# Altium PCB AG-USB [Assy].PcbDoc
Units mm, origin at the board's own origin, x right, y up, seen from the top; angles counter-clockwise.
Board outline 22 x 85.18 mm, 2 copper layers (Top Layer, Bottom Layer), stack 1.571 mm thick; 0 components, 8 nets, 0 pads, 0 vias.
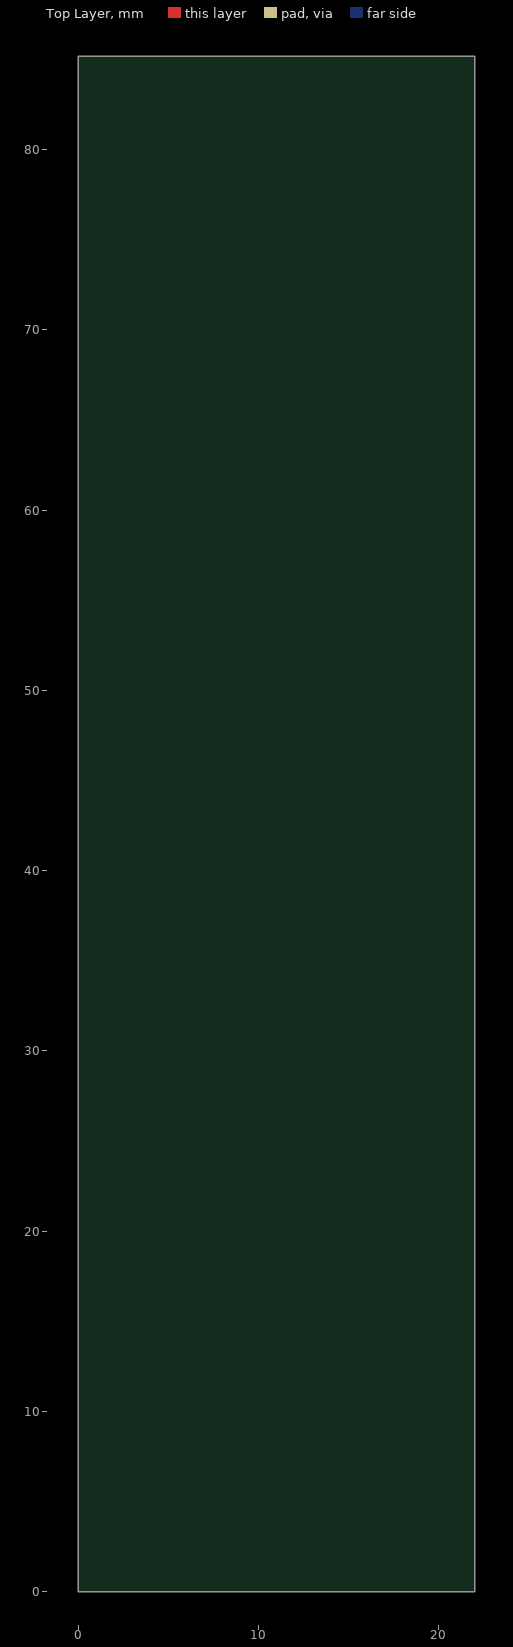
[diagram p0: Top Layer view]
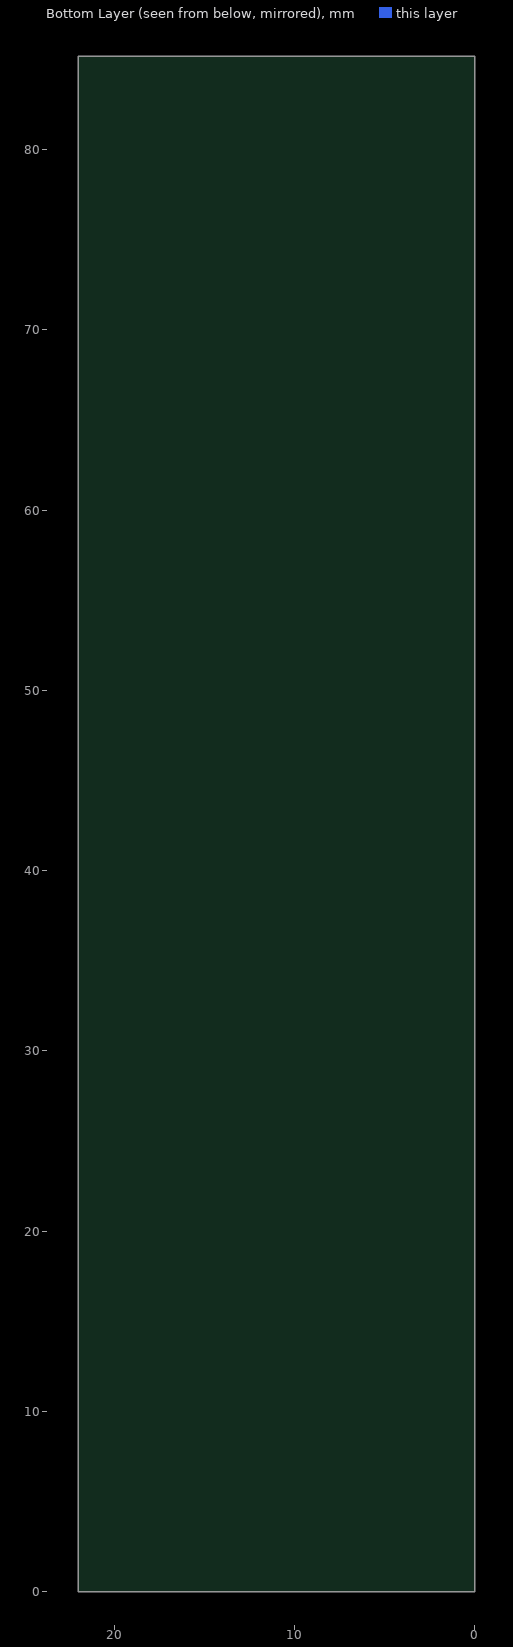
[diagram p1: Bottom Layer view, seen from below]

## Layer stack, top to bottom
Top Layer: signal copper 0.0356
Dielectric: prepreg 1.5, FR-4, Dk 4.2
Bottom Layer: signal copper 0.0356

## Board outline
0,0 0,85.18 22,85.18 22,0

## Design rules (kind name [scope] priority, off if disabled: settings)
Clearance [All] p1: gap=0.17
FabricationTestPointUsage TestPointUsage [All] p1: valid=0 allowmultiple=FALSE
FabricationTestpoint Testpoint [All] p1: side=3 testpointundercomponent=TRUE minsize=1.016 maxsize=2.54 preferedsize=1.524 minholesize=0 maxholesize=1.016 preferedholesize=0.813 testpointgrid=0.025 allowsidetop=TRUE allowsidebottom=TRUE usegrid=TRUE gridtolerance=0
HoleSize [All] p1: absolutevalues=TRUE maxlimit=5 minlimit=0.25 maxpercent=80.000 minpercent=20.000
PlaneClearance [All] p1: clearance=0.5
PolygonConnect PolygonConnectVia [All vs isvia] p1: connectstyle=Direct reliefconductorwidth=0.25 reliefentries=4 polygonreliefangle="90 Angle" airgapwidth=0.254
PolygonConnect [All] p2: connectstyle=Relief reliefconductorwidth=0.4 reliefentries=4 polygonreliefangle="90 Angle" airgapwidth=0.254
RoutingCorners [All] p1: cornerstyle=45-Degree minsetback=2.5 maxsetback=2.5
RoutingVias [All] p1: holewidth=0.3 width=0.7 viastyle="Through Hole" minholewidth=0.3 minwidth=0.7 maxholewidth=0.3 maxwidth=0.7
SilkToSolderMaskClearance SilkscreenOverComponentPads [IsPad] p1: minsilkscreentomaskgap=0.254 clearancetoexposedcopper=TRUE
SolderMaskExpansion [All] p1: expansion=0.05
Width "Width_High Power" [InNetClass('High Power')] p1: maxlimit=1.5 minlimit=0.5 preferedwidth=1
Width Width_Power [InNetClass('Power')] p2: maxlimit=1 minlimit=0.3 preferedwidth=0.5
Width [All] p3: maxlimit=2 minlimit=0.2 preferedwidth=0.2
22 further rules are at their usual default settings.

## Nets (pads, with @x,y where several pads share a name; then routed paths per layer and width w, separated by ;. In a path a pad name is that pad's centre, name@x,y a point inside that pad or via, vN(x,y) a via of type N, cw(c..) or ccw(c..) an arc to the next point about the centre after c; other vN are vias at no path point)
NetA1_1: 
NetA2_1: 
NetA3_1: 
NetA4_1: 
NetB1_1: 
NetB2_1: 
NetB3_1: 
NetB4_1: 

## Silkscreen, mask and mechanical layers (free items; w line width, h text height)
Top Assy 1:
  circle w0.125: c0.001,-0.016 r2
  lines w0.2: -104.22,-49.817 -47.22,-49.817 ; -91.72,-54.817 -91.72,-49.817 ; -47.22,-44.817 48.78,-44.817 139.78,-44.817 ; -47.22,-39.817 48.78,-39.817 ; -47.22,-34.817 48.78,-34.817 ; -47.22,-29.817 48.78,-29.817 ; -31.22,-54.817 -31.22,-24.817 ; -15.22,-24.817 -15.22,-54.817 -15.22,-49.817 ; -14.999,9.984 -12.999,9.984 ; -14.999,19.984 -12.999,19.984 ; -14.999,29.956 -14.999,89.916 ; -14.999,29.984 -12.999,29.984 ; -14.999,39.984 -12.999,39.984 ; -14.999,49.956 -14.999,89.789 ; -14.999,49.984 -12.999,49.984 ; -14.999,59.984 -12.999,59.984 ; -14.999,69.977 -14.999,-0.016 -12.999,-0.016 ; -14.999,69.984 -12.999,69.984 ; -14.999,79.956 -12.999,79.956 ; -14.999,89.956 -12.999,89.956 ; -2.999,-0.016 -0.999,-0.016 ; 0.001,-13.016 0.001,-15.016 29.972,-15.016 ; 0.001,-3.016 0.001,-1.016 ; 0.78,-54.817 0.78,-24.817 ; 10.001,-15.016 10.001,-13.016 ; 16.78,-54.817 16.78,-24.817 ; 20.001,-15.016 20.001,-13.016 ; 30.001,-15.016 30.001,-13.016 ; 32.78,-54.817 32.78,-24.817 ; 66.78,-54.817 66.78,-44.817 ; 104.78,-54.817 104.78,-44.817 ; 117.78,-54.817 117.78,-44.817 ; 139.78,-49.817 48.78,-49.817 32.78,-49.817 16.78,-49.817 0.78,-49.817 -15.22,-49.817 ; -47.22,-54.817 -47.22,-49.817 ; -47.22,-54.817 -47.22,-49.817 ; -47.22,-54.817 -47.22,-49.817 ; -47.22,-49.817 -31.22,-49.817 -15.22,-49.817 ; -47.22,-49.817 -47.22,-24.817 ; -47.22,-24.817 48.78,-24.817 ; -47.22,-24.817 -63.22,-24.817 -104.22,-24.817 -104.22,-54.817 48.78,-54.817 ; 48.78,-54.817 139.78,-54.817 139.78,-24.817 48.78,-24.817 ; 48.78,-54.817 48.78,-24.817
  text "90" at -11.999,88.956 h2.5
  text "80" at -11.999,78.956 h2.5
  text "70" at -11.999,68.984 h2.5
  text "60" at -11.999,58.984 h2.5
  text "50" at -11.999,48.984 h2.5
  text "40" at -11.999,38.984 h2.5
  text "30" at -11.999,28.984 h2.5
  text "20" at -11.999,18.984 h2.5
  text "10" at -11.999,8.984 h2.5
  text "0" at -11.999,-1.016 h2.5
  text "0" at 1.001,-12.016 h2.5 r90
  text "10" at 11.001,-12.016 h2.5 r90
  text "20" at 21.001,-12.016 h2.5 r90
  text "30" at 31.001,-12.016 h2.5 r90
  text "TITLE" at 50.78,-27.817 h2.5
  text "AGRIGEL" at -99.995,-34.241 h10
  text ".PCB_TITLE" at 53.78,-35.817 h5
  text "TOP SIDE PLACEMENT" at 53.78,-39.817 h2.5
  text ".PCB_Drawn" at -43.22,-47.817 h2.5
  text ".PCB_Checked" at -28.22,-47.817 h2.5
  text ".PCB_Approved" at -12.22,-47.817 h2.5
  text ".PRINT_DATE" at 3.78,-47.817 h2.5
  text ".PCB_DocRevision" at 17.78,-47.817 h2.5
  text ".PCB_ECRNo" at 36.78,-47.817 h2.5
  text "DWG NUMBER" at 49.78,-47.817 h2.5
  text ".PCB_Drawing Number" at 68.78,-47.817 h2.5
  text "PCB VER" at 105.78,-47.817 h2.5
  text "SHEET NO." at 119.78,-47.817 h2.5
  text "PLOTFILE" at -103.22,-52.817 h2.5
  text ".PCB_Plot File [Assy]" at -90.72,-52.817 h2.5
  text "DRAWN" at -43.22,-52.817 h2.5
  text "CHECKED" at -28.22,-52.817 h2.5
  text "APPROVED" at -13.22,-52.817 h2.5
  text "DATE" at 5.78,-52.817 h2.5
  text "DOC REV." at 19.78,-52.817 h2.5
  text "ECR NO." at 36.78,-52.817 h2.5
  text "SOURCE" at 49.78,-52.817 h2.5
  text ".Pcb_File_Name_No_Path" at 68.78,-52.817 h2.5
  text ".Version" at 107.78,-52.817 h2.5
  text "SHEET" at 119.78,-52.817 h2.5
  text "1" at 128.78,-52.817 h2.5
  text "OF" at 131.78,-52.817 h2.5
  text "2" at 136.78,-52.817 h2.5
Bot Assy 1:
  circle w0.125: c0.073,-0.016 r2
  lines w0.2: -104.173,-49.864 -13.173,-49.864 2.827,-49.864 18.827,-49.864 34.827,-49.864 50.827,-49.864 ; -104.173,-44.864 -13.173,-44.864 82.827,-44.864 ; -82.173,-54.864 -82.173,-44.864 ; -69.173,-54.864 -69.173,-44.864 ; -31.173,-54.864 -31.173,-44.864 ; -14.927,9.984 -12.927,9.984 ; -14.927,19.984 -12.927,19.984 ; -14.927,29.956 -14.927,89.916 ; -14.927,29.984 -12.927,29.984 ; -14.927,39.984 -12.927,39.984 ; -14.927,49.956 -14.927,89.789 ; -14.927,49.984 -12.927,49.984 ; -14.927,59.984 -12.927,59.984 ; -14.927,69.977 -14.927,-0.016 -12.927,-0.016 ; -14.927,69.984 -12.927,69.984 ; -14.927,79.956 -12.927,79.956 ; -14.927,89.956 -12.927,89.956 ; -13.173,-39.864 82.827,-39.864 ; -13.173,-34.864 82.827,-34.864 ; -13.173,-29.864 82.827,-29.864 ; -2.927,-0.016 -0.927,-0.016 ; 0.073,-13.016 0.073,-15.016 30.044,-15.016 ; 0.073,-3.016 0.073,-1.016 ; 2.827,-54.864 2.827,-24.864 ; 10.073,-15.016 10.073,-13.016 ; 18.827,-54.864 18.827,-24.864 ; 20.073,-15.016 20.073,-13.016 ; 30.073,-15.016 30.073,-13.016 ; 34.827,-54.864 34.827,-24.864 ; 50.827,-24.864 50.827,-54.864 50.827,-49.864 ; 66.827,-54.864 66.827,-24.864 ; 127.327,-54.864 127.327,-49.864 ; 139.827,-49.864 82.827,-49.864 ; -13.173,-54.864 -104.173,-54.864 -104.173,-24.864 -13.173,-24.864 ; -13.173,-54.864 -13.173,-24.864 ; -13.173,-54.864 139.827,-54.864 139.827,-24.864 98.827,-24.864 82.827,-24.864 ; -13.173,-24.864 82.827,-24.864 ; 50.827,-49.864 66.827,-49.864 82.827,-49.864 ; 82.827,-54.864 82.827,-49.864 ; 82.827,-54.864 82.827,-49.864 ; 82.827,-54.864 82.827,-49.864 ; 82.827,-49.864 82.827,-24.864
  text "90" at -9.387,88.956 h2.5
  text "80" at -9.387,78.956 h2.5
  text "70" at -9.387,68.984 h2.5
  text "60" at -9.387,58.984 h2.5
  text "50" at -9.387,48.984 h2.5
  text "40" at -9.387,38.984 h2.5
  text "30" at -9.387,28.984 h2.5
  text "20" at -9.387,18.984 h2.5
  text "10" at -9.387,8.984 h2.5
  text "0" at -10.922,-1.016 h2.5
  text "10" at 11.073,-9.476 h2.5 r90
  text "20" at 21.073,-9.476 h2.5 r90
  text "30" at 31.073,-9.476 h2.5 r90
  text "0" at 1.016,-10.922 h2.5 r90
  text "TITLE" at -15.173,-27.864 h2.5
  text "AGRIGEL" at 135.555,-34.368 h10
  text ".PCB_TITLE" at -18.173,-35.864 h5
  text "BOTTOM SIDE PLACEMENT" at -18.173,-39.864 h2.5
  text "SHEET NO." at -84.173,-47.864 h2.5
  text "PCB VER" at -70.173,-47.864 h2.5
  text ".PCB_Drawing Number" at -33.173,-47.864 h2.5
  text "DWG NUMBER" at -14.173,-47.864 h2.5
  text ".PCB_ECRNo" at -1.173,-47.864 h2.5
  text ".PCB_DocRevision" at 17.827,-47.864 h2.5
  text ".PRINT_DATE" at 31.827,-47.864 h2.5
  text ".PCB_Approved" at 47.827,-47.864 h2.5
  text ".PCB_Checked" at 63.827,-47.864 h2.5
  text ".PCB_Drawn" at 78.827,-47.864 h2.5
  text "2" at -101.173,-52.864 h2.5
  text "OF" at -96.173,-52.864 h2.5
  text "2" at -93.173,-52.864 h2.5
  text "SHEET" at -84.173,-52.864 h2.5
  text ".Version" at -72.173,-52.864 h2.5
  text ".Pcb_File_Name_No_Path" at -33.173,-52.864 h2.5
  text "SOURCE" at -14.173,-52.864 h2.5
  text "ECR NO." at -1.173,-52.864 h2.5
  text "DOC REV." at 15.827,-52.864 h2.5
  text "DATE" at 29.827,-52.864 h2.5
  text "APPROVED" at 48.827,-52.864 h2.5
  text "CHECKED" at 63.827,-52.864 h2.5
  text "DRAWN" at 78.827,-52.864 h2.5
  text ".PCB_Plot File [Assy]" at 126.327,-52.864 h2.5
  text "PLOTFILE" at 138.827,-52.864 h2.5

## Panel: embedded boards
"AG-USB.PcbDoc" at 0,0, 1 rows x 1 columns, spacing 85.18 x 22, rotation 0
